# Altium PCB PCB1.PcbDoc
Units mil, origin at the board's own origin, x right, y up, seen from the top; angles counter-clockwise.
Board outline 2600 x 2600 mil, 4 copper layers (Top Layer, Layer 1, Layer 2, Bottom Layer), stack 68.756 mil thick; 75 components, 74 nets, 370 pads, 169 vias.
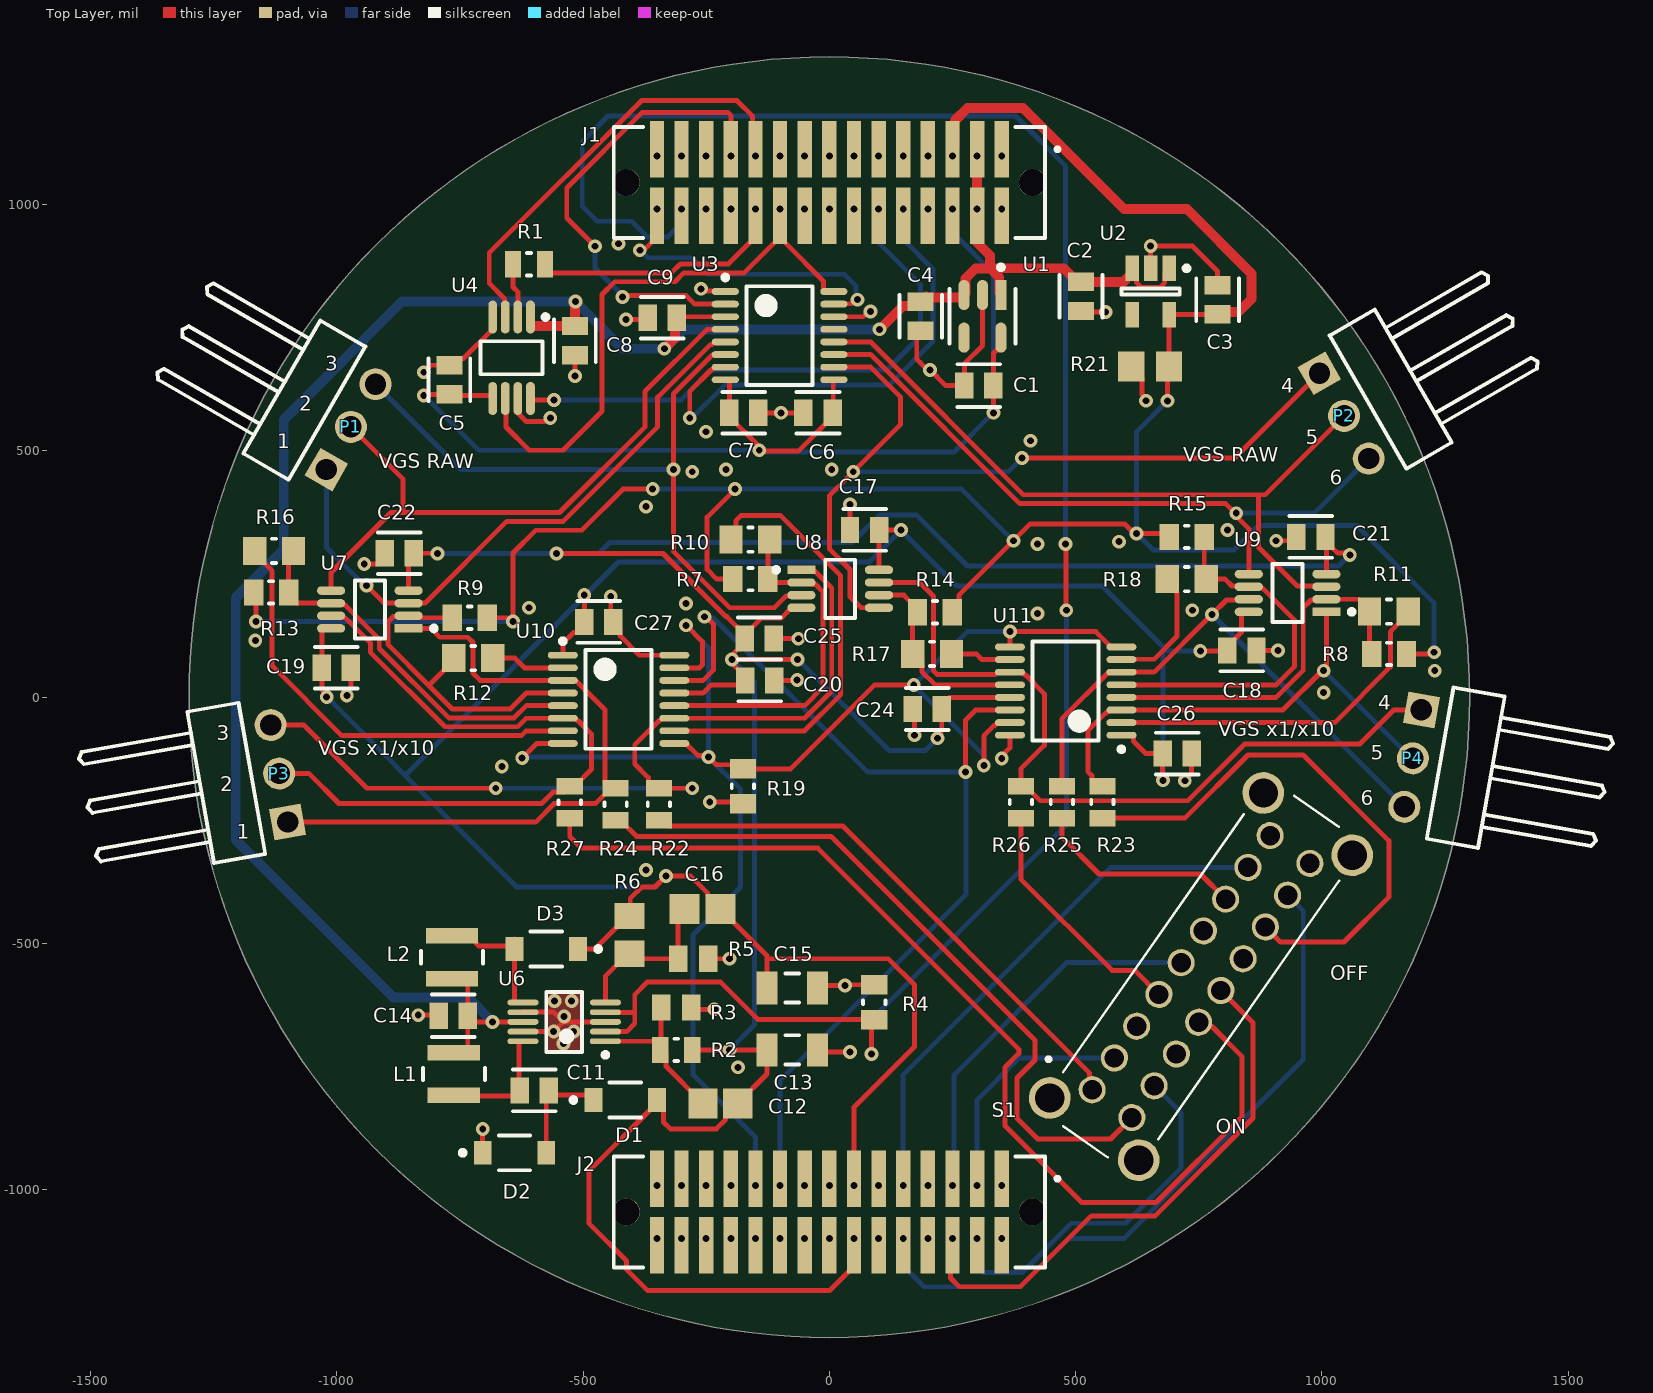
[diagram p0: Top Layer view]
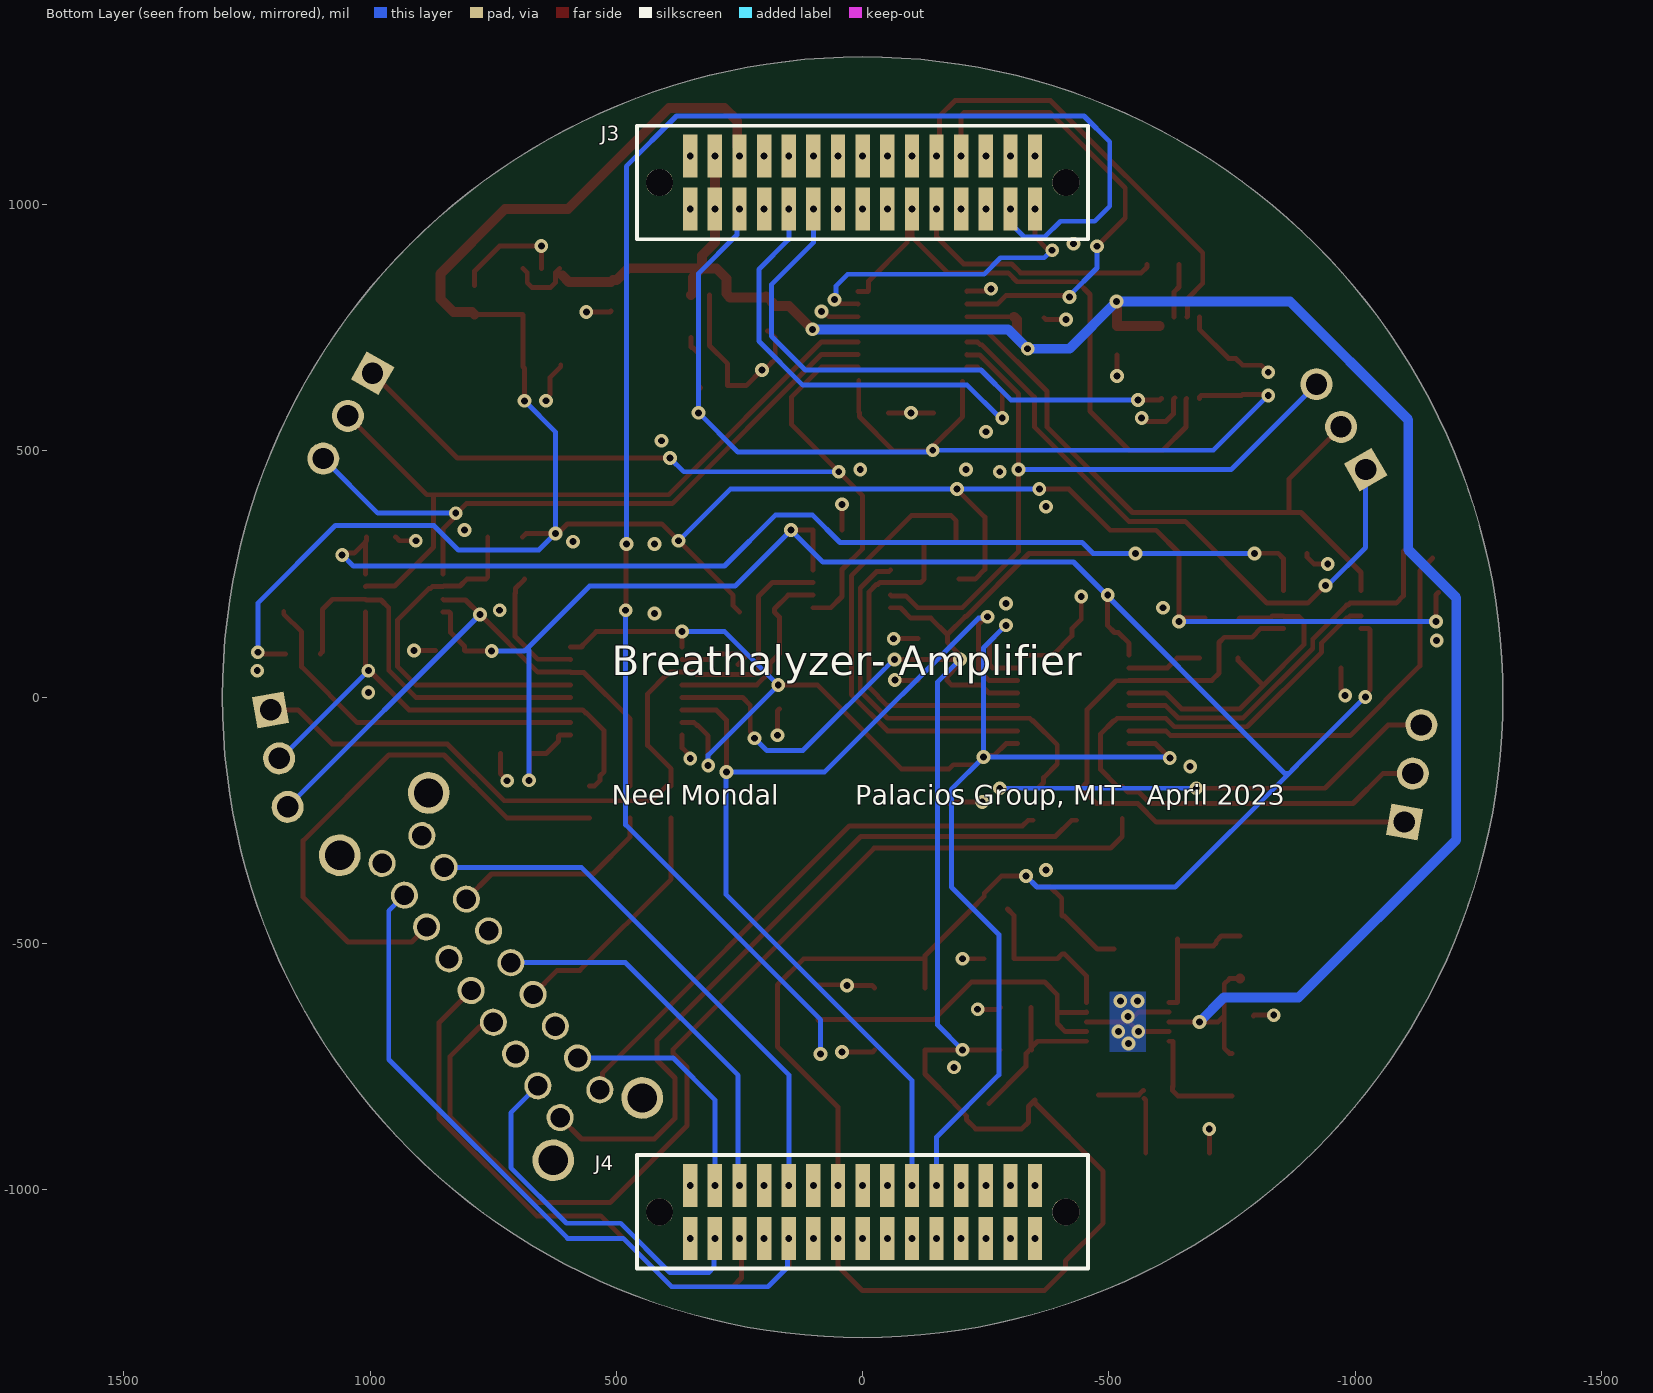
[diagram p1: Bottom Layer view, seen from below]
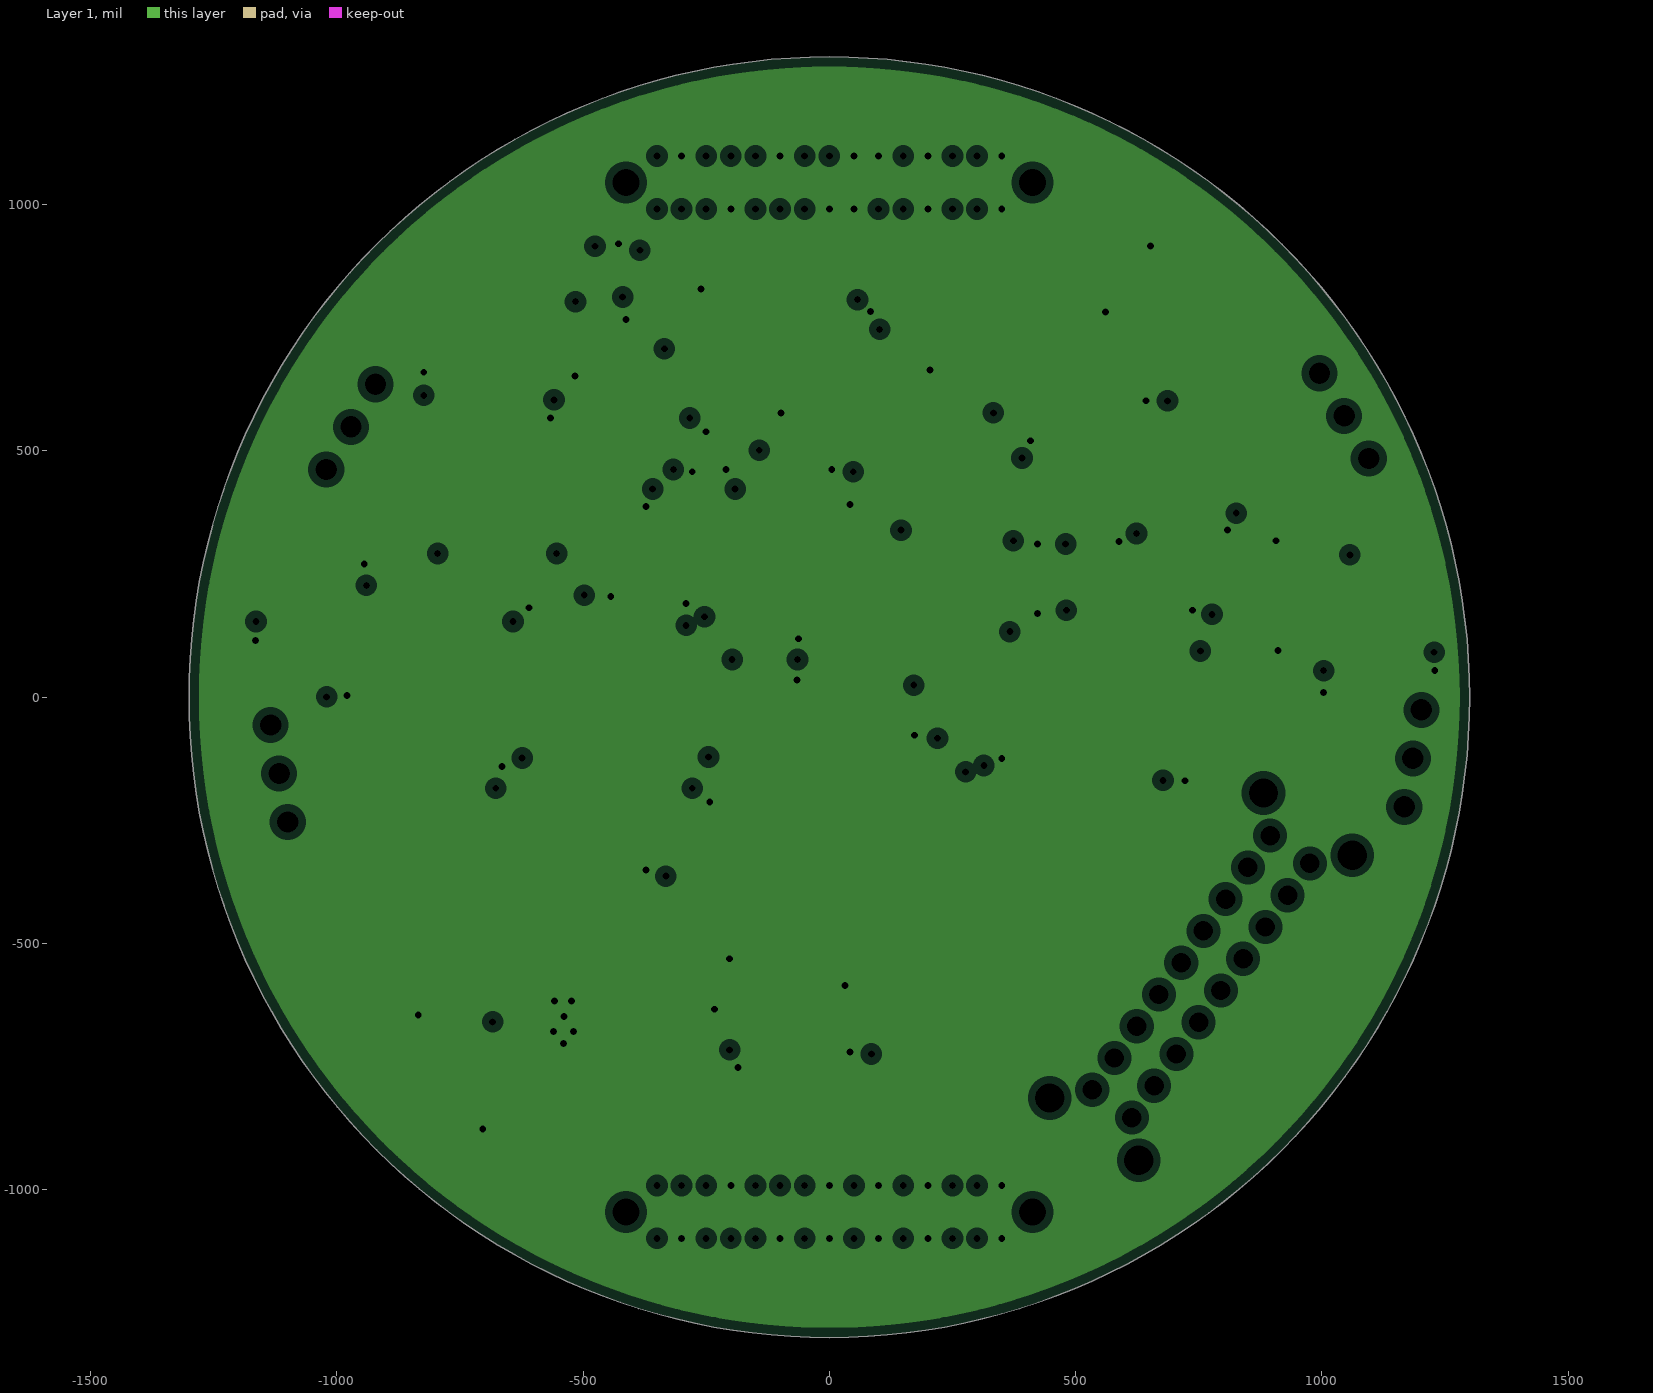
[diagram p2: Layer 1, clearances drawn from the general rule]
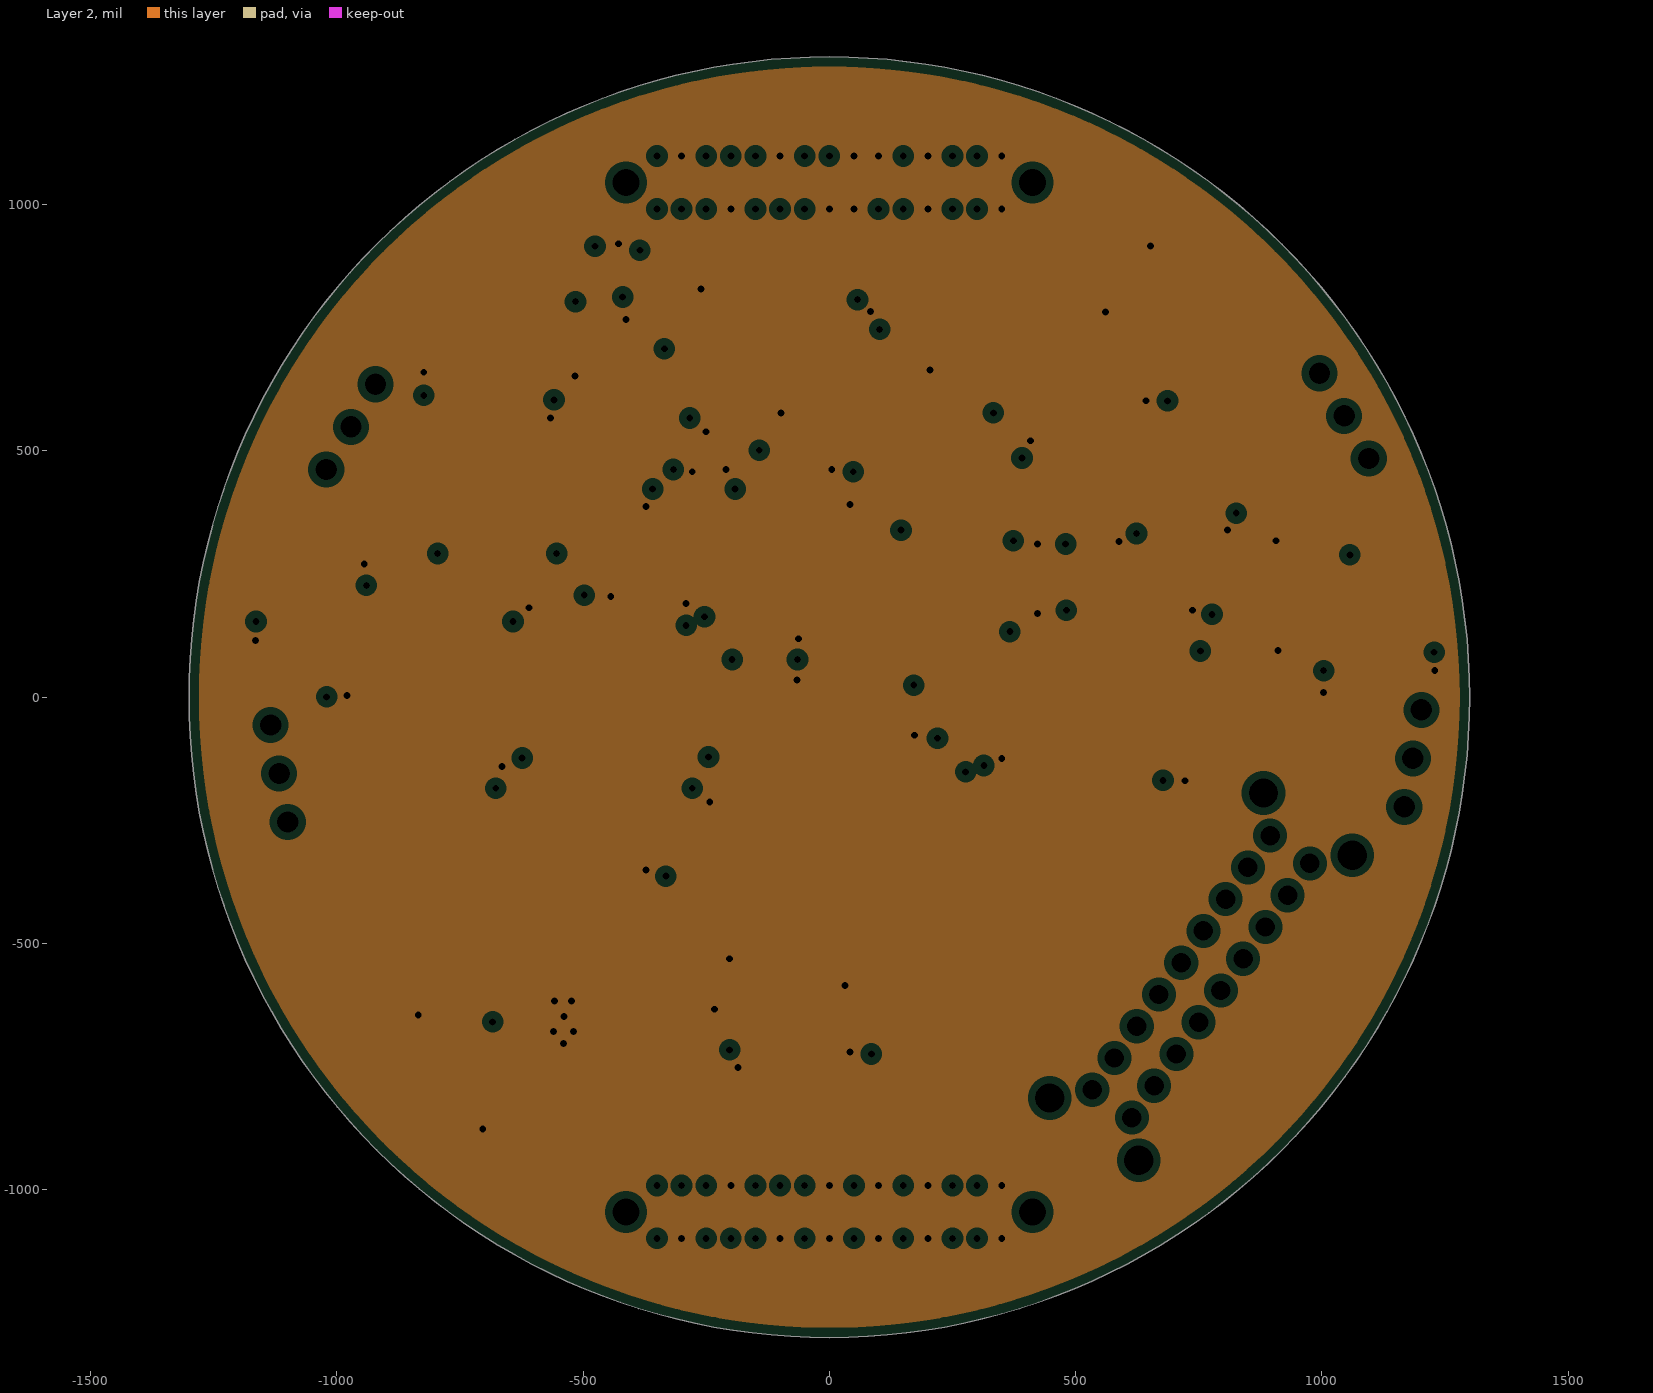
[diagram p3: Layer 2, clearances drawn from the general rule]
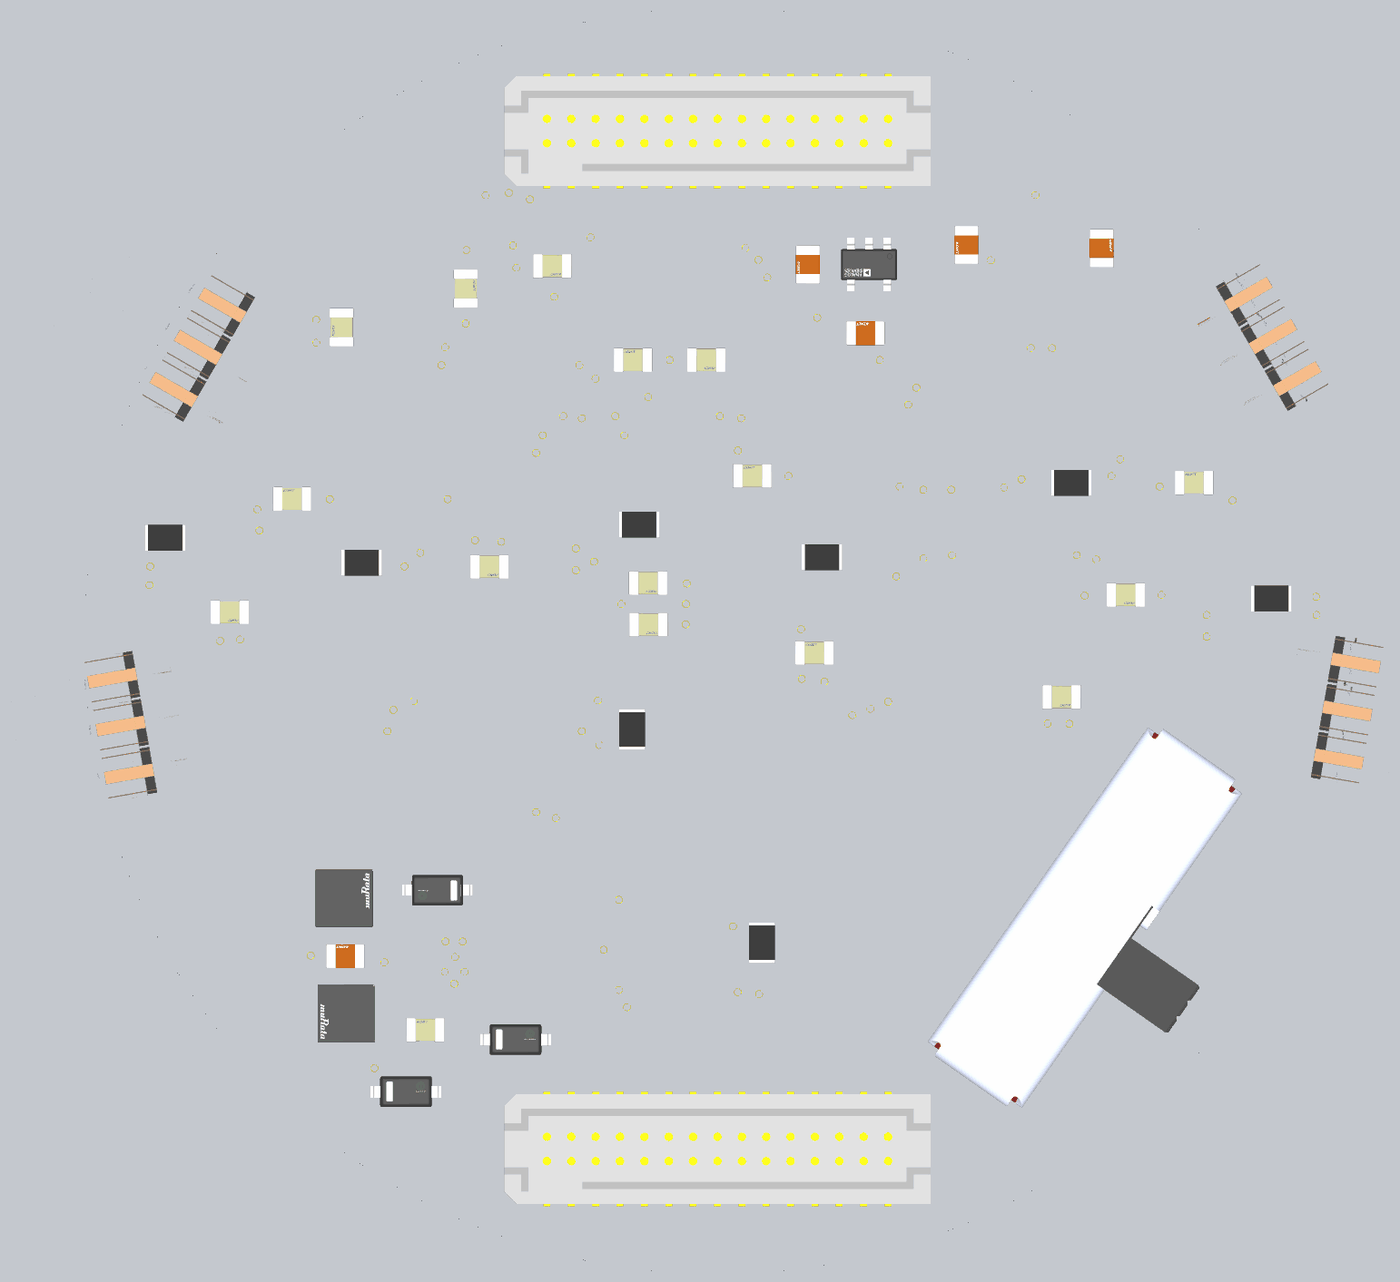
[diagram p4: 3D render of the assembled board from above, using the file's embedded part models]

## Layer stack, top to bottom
Top Solder: solder mask 0.5, Solder Resist, Dk 3.3
Top Layer: signal copper 0.7
Dielectric 1: prepreg 2.8, PP-006, Dk 4.1
Layer 1: plane copper 1.378, net GND
Dielectric1: core 59, FR-4, Dk 4.3
Layer 2: plane copper 1.378, net GND
Dielectric 2: prepreg 2.8, PP-006, Dk 4.1
Bottom Layer: signal copper 0.7
Bottom Solder: solder mask 0.5, Solder Resist, Dk 3.3

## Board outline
-1300,0 ccw(c0,0) 0,-1300 ccw(c0,0) 1300,0 ccw(c0,0) 0,1300 ccw(c0,0)

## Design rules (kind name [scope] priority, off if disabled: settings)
Clearance [All] p1: gap=8 ignorepadtopadclearanceinfootprint=FALSE except(6: SMDPad-SMDPad; 12: Arc-Via Track-Via)
DiffPairsRouting [All] p1: maxlimit=10 minlimit=10 mostfreqgap=10 toplayer_minwidth=10 toplayer_maxwidth=10 toplayer_prefwidth=10 bottomlayer_minwidth=10 bottomlayer_maxwidth=10 bottomlayer_prefwidth=10 maxuncoupledlength=500
HoleSize [All] p1: absolutevalues=TRUE maxlimit=300 minlimit=10 maxpercent=80.000 minpercent=20.000
MinimumAnnularRing [All] p1: minimumring=7
MinimumSolderMaskSliver [All] p1: minsoldermaskwidth=0
PasteMaskExpansion [All] p1: expansion=10
PlaneClearance [All] p1: clearance=15
PlaneConnect [All] p1: pad.planeconnectstyle=Relief pad.reliefexpansion=20 pad.reliefentries=4 pad.reliefconductorwidth=10 pad.reliefairgap=10 via.planeconnectstyle=Direct via.reliefexpansion=20 via.reliefentries=4 via.reliefconductorwidth=10 via.reliefairgap=10
PolygonConnect [All] p1: thpad.connectstyle=Relief thpad.reliefconductorwidth=10 thpad.reliefentries=4 thpad.polygonreliefangle="90 Angle" thpad.airgapwidth=10 smdpad.connectstyle=Relief smdpad.reliefconductorwidth=10 smdpad.reliefentries=4 smdpad.polygonreliefangle="90 Angle" smdpad.airgapwidth=10 via.connectstyle=Direct via.reliefconductorwidth=10 via.reliefentries=4 via.polygonreliefangle="90 Angle" via.airgapwidth=10
RoutingVias [All] p1: holewidth=14 width=28 viastyle="Through Hole" minholewidth=14 minwidth=28 maxholewidth=14 maxwidth=28
SMDNeckDown [All] p1: percent=150.000
SilkToSolderMaskClearance SilkscreenOverComponentPads [IsPad] p1: minsilkscreentomaskgap=0 clearancetoexposedcopper=TRUE
SolderMaskExpansion [All] p1: expansion=10 istentingtop=FALSE
Width [All] p1: maxlimit=30 minlimit=10 preferedwidth=10
23 further rules are at their usual default settings.

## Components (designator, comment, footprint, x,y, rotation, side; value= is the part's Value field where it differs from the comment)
C1 "4.7 uF" FP-C0805C475K3PACTU-MFG 303.55,632.61 r180 top
C2 "4.7 uF" FP-C0805C475K3PACTU-MFG 510.93,813.62 r270 top
C3 "4.7 uF" FP-C0805C475K3PACTU-MFG 788.14,806.63 r90 top
C4 "4.7 uF" FP-C0805C475K3PACTU-MFG 185.43,773.3 r270 top
C5 "100 nF" FP-C0805C-DN-MFG -771.4,644.43 r90 top value="0.10 μF"
C6 "100 nF" FP-C0805C-DN-MFG -22.98,577.3 r180 top value="0.10 μF"
C7 "100 nF" FP-C0805C-DN-MFG -173.44,577.3 r0 top value="0.10 μF"
C8 "100 nF" FP-C0805C-DN-MFG -516.6,724.07 r270 top value="0.10 μF"
C9 "100 nF" FP-C0805C-DN-MFG -338.91,770.32 r180 top value="0.10 μF"
C11 "100 nF" FP-C0805C-DN-MFG -599.3,-798.23 r0 top value="0.10 μF"
C12 "100 pF" CAPC2013X140X50ML20T25 -221.28,-825.33 r180 top
C13 "1 uF" CAPC3216X110X50LL20T25 -75.35,-716 r180 top
C14 "4.7 uF" FP-C0805C475K3PACTU-MFG -763.65,-646.88 r180 top
C15 "1 uF" CAPC3216X110X50LL20T25 -75.35,-590.33 r0 top
C16 "4.7 pF" CAPC2013X71X50ML20T25 -257.7,-430 r180 top
C17 "100 nF" FP-C0805C-DN-MFG 71.54,339.52 r0 top value="0.10 μF"
C18 "100 nF" FP-C0805C-DN-MFG 837.7,95.04 r180 top value="0.10 μF"
C19 "100 nF" FP-C0805C-DN-MFG -1000.79,59.61 r180 top value="0.10 μF"
C20 "100 nF" FP-C0805C-DN-MFG -142.28,119.39 r180 top value="0.10 μF"
C21 "100 nF" FP-C0805C-DN-MFG 977.8,325.4 r0 top value="0.10 μF"
C22 "100 nF" FP-C0805C-DN-MFG -872.87,292.18 r0 top value="0.10 μF"
C24 "100 nF" FP-C0805C-DN-MFG 198.75,-24.05 r0 top value="0.10 μF"
C25 "100 nF" FP-C0805C-DN-MFG -141.55,34.02 r180 top value="0.10 μF"
C26 "100 nF" FP-C0805C-DN-MFG 706.14,-114.6 r180 top value="0.10 μF"
C27 "100 nF" FP-C0805C-DN-MFG -467.94,152.85 r180 top value="0.10 μF"
D1 "MBR0530" FP-425-04-MFG -414.26,-817.92 r0 top
D2 "MBR0530" FP-425-04-MFG -639.2,-925.01 r0 top
D3 "MBR0530" FP-425-04-MFG -574.7,-511.32 r180 top
J1 "TFM-115-02-L-D" SAMTEC_TFM-115-02-L-D 0,1045 r180 top locked
J2 "TFM-115-02-L-D" SAMTEC_TFM-115-02-L-D 0,-1045 r180 top locked
J3 "SAMTEC-SFM-115-02-X-D-A" SAMTEC-SFM-115-02-X-D-A 0,1045 r180 bottom locked
J4 "SAMTEC-SFM-115-02-X-D-A" SAMTEC-SFM-115-02-X-D-A 0,-1045 r180 bottom locked
L1 "LQH3NPN100MMEL" FP-LQH3NPH_ME-MFG -762.28,-765.03 r270 top
L2 "LQH3NPN100MMEL" FP-LQH3NPH_ME-MFG -765.93,-528 r90 top
P1 "DNP" 61300311021 -1065.71,603.29 r240 top locked
P2 "DNP" 61300311021 1139.57,625.61 r120 top locked
P3 "DNP" 61300311021 -1224.37,-174.02 r280 top locked
P4 "DNP" 61300311021 1292.09,-143.15 r80 top locked
R1 "100" RESC2013X50X30LL20T20 -609.72,878.95 r0 top
R2 "196k" RESC2013X50X30LL20T20 -310.85,-716 r0 top
R3 "24.9k" RESC2013X70X40LL20T20 -310.85,-629.7 r180 top
R4 "10k" RESC2013X60X35NL10T20 91.23,-619.2 r270 top
R5 "24.9k" RESC2013X70X40LL20T20 -276.4,-531 r0 top
R6 "220k" RESC2013X70X40ML20T20 -405.41,-482.62 r270 top
R7 "10k" RESC2013X60X35NL10T20 -160.25,239.7 r180 top
R8 "10k" RESC2013X60X35NL10T20 1136.45,87.89 r0 top
R9 "10k" RESC2013X60X35NL10T20 -730.06,161.26 r0 top
R10 "91k" RESC2013X60X35ML10T20 -160.25,319.84 r180 top
R11 "91k" RESC2013X60X35ML10T20 1136.05,173.63 r0 top
R12 "91k" RESC2013X60X35ML10T20 -722.91,79.29 r0 top
R13 "10k" RESC2013X60X35NL10T20 -1133.28,212.62 r180 top
R14 "10k" RESC2013X60X35NL10T20 214.49,172.54 r0 top
R15 "10k" RESC2013X60X35NL10T20 725.83,325.4 r180 top
R16 "91k" RESC2013X60X35ML10T20 -1127.38,297.09 r180 top
R17 "91k" RESC2013X60X35ML10T20 208.59,87.89 r0 top
R18 "91k" RESC2013X60X35ML10T20 725.68,239.7 r180 top
R19 "10k" RESC2013X60X35NL10T20 -175.45,-180.91 r270 top
R21 "470" RESC2013X70X40ML20T20 651.43,671 r0 top
R22 "100" RESC2013X50X30LL20T20 -345.91,-217.33 r270 top
R23 "100" RESC2013X50X30LL20T20 554.46,-212.97 r270 top
R24 "100" RESC2013X50X30LL20T20 -433.95,-217.33 r270 top
R25 "100" RESC2013X50X30LL20T20 472.14,-212.97 r270 top
R26 "100" RESC2013X50X30LL20T20 389,-212.97 r270 top
R27 "100" RESC2013X50X30LL20T20 -527,-213.39 r270 top
S1 "EG6201" SW_EG6201 754.65,-567.27 r55 top
U1 "ADP150AUJZ-2.0-R7" FP-UJ-5-IPC_B 310.96,773.3 r270 top
U2 "LD39015M10R" SOT23-5L_M 652.41,823.47 r270 top
U3 "AD5328BRUZ" RU-16_L -100.98,733.99 r0 top
U4 "AD7274BRMZ" RM-8_N -645.16,689.05 r270 top
U6 "LT1945EMS#PBF" LT-MS-10_N -538.28,-659.23 r180 top
U7 "ADA4522-2ARMZ" FP-RM-8-IPC_C -932.84,178 r180 top
U8 "ADA4522-2ARMZ" FP-RM-8-IPC_C 22.07,220.01 r0 top
U9 "ADA4522-2ARMZ" FP-RM-8-IPC_C 930.41,211.56 r180 top
U10 "ADG5433BRUZ" ADI-RU-16_N -427.93,-4.37 r0 top
U11 "ADG5433BRUZ" ADI-RU-16_N 479.76,12.36 r180 top

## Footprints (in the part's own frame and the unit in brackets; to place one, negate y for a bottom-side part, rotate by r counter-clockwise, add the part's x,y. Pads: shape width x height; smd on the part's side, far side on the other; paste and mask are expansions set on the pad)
61300311021 [mm] "Pin Header, pitch 2.54 mm, THT, Angled, single row, 3p"
  rect 1.65x1.65 hole 1.1: 1(2.54,2.77)
  round 1.65 hole 1.1: 2(0,2.77) 3(-2.54,2.77)
  silkscreen extent -3.96,-7.27 3.96,1.34, body extent -3.81,-7.27 3.81,3.09, height 2.58
ADI-RU-16_N [mm] "SOP, 16-Leads, Body 5x4.4mm, Pitch 0.65mm, IPC Medium Density"
  oval 1.55x0.35 smd: 1(-2.875,2.275) 2(-2.875,1.625) 3(-2.875,0.975) 4(-2.875,0.325) 5(-2.875,-0.325) 6(-2.875,-0.975) 7(-2.875,-1.625) 8(-2.875,-2.275) 9(2.875,-2.275) 10(2.875,-1.625) 11(2.875,-0.975) 12(2.875,-0.325) 13(2.875,0.325) 14(2.875,0.975) 15(2.875,1.625) 16(2.875,2.275)
  silkscreen extent -3,-2.55 1.7,3.12, body extent -2.25,-2.55 2.25,2.55, height 1.2
CAPC2013X71X50ML20T25 [mm] "Chip Capacitor, 2-Leads, Body 2.01x1.25mm, IPC Low Density"
  rect 1.55x1.55 smd: 1(-0.925,0) 2(0.925,0)
  body extent -1.1,-0.73 1.11,0.73, height 0.71
CAPC2013X140X50ML20T25 [mm] "Chip Capacitor, 2-Leads, Body 2.00x1.25mm, IPC Low Density"
  rect 1.5x1.55 smd: 1(-0.9,0) 2(0.9,0)
  body extent -1.1,-0.72 1.1,0.72, height 1.4
CAPC3216X110X50LL20T25 [mm] "Chip Capacitor, 2-Leads, Body 3.20x1.60mm, IPC High Density"
  rect 1.1x1.7 smd: 1(-1.3,0) 2(1.3,0)
  silkscreen extent -0.35,-0.75 0.35,0.75, body extent -1.7,-0.9 1.7,0.9, height 1.1
FP-425-04-MFG [mil]
  rect 36x48 smd paste+0 mask+0: 1(-64.5,0) 2(64.5,0)
  silkscreen extent -110,-35 32,35, body extent -86,-39 86,39, height 10
FP-C0805C475K3PACTU-MFG [mm]
  rect 0.95x1.35 smd paste+0 mask+0: 1(-0.75,0) 2(0.75,0)
  silkscreen extent -1.1,-1.1 1.1,1.1, body extent -1.4,-0.85 1.4,0.85, height 0.25
FP-C0805C-DN-MFG [mm]
  rect 0.95x1.35 smd paste+0 mask+0: 1(-0.75,0) 2(0.75,0)
  silkscreen extent -1.1,-1.07 1.1,1.07, body extent -1.4,-0.85 1.4,0.85, height 0.25
FP-LQH3NPH_ME-MFG [mm]
  rect 0.8x2.7 smd paste+0 mask+0: 1(-1.1,0) 2(1.1,0)
  silkscreen extent -0.33,-1.6 0.33,1.6, body extent -1.7,-1.7 1.7,1.7, height 0.25
FP-RM-8-IPC_C [mm]
  rect 1.454x0.436 smd paste+0 mask+0: 1(-2,0.975)
  rrect100% 1.454x0.436 smd paste+0 mask+0: 2(-2,0.325) 3(-2,-0.325) 4(-2,-0.975) 5(2,-0.975) 6(2,-0.325) 7(2,0.325) 8(2,0.975)
  silkscreen extent -3.43,-1.5 0.77,1.5
FP-UJ-5-IPC_B [mm]
  rect 1.554x0.572 smd paste+0 mask+0: 1(-1.1,0.95)
  rrect100% 1.554x0.572 smd paste+0 mask+0: 2(-1.1,0) 3(-1.1,-0.95) 4(1.1,-0.95) 5(1.1,0.95)
  silkscreen extent -2.65,-1.7 1.4,1.7, body extent -2.13,-1.7 2.13,1.7, height 0.25
LT-MS-10_N [mm] "SOP, 10-Leads, Body 3.1x3.1mm, Pitch 0.5mm, IPC Medium Density"
  oval 1.6x0.3 smd: 1(-2.125,1) 2(-2.125,0.5) 3(-2.125,0) 4(-2.125,-0.5) 5(-2.125,-1) 6(2.125,-1) 7(2.125,-0.5) 8(2.125,0) 9(2.125,0.5) 10(2.125,1)
  silkscreen extent -2.25,-1.55 0.92,1.82, body extent -1.55,-1.55 1.55,1.55, height 1.1
RESC2013X50X30LL20T20 [mm] "Chip Resistor, 2-Leads, Body 2.00x1.25mm, IPC High Density"
  rect 0.85x1.35 smd: 1(-0.825,0) 2(0.825,0)
  silkscreen extent -0.1,-0.58 0.1,0.58, body extent -1.1,-0.73 1.1,0.73, height 0.5
RESC2013X60X35ML10T20 [mm] "Chip Resistor, 2-Leads, Body 2.00x1.25mm, IPC Low Density"
  rect 1.2x1.45 smd: 1(-1,0) 2(1,0)
  silkscreen extent -0.1,-0.63 0.1,0.63, body extent -1.05,-0.67 1.05,0.67, height 0.6
RESC2013X60X35NL10T20 [mm] "Chip Resistor, 2-Leads, Body 2.1x1.35mm, IPC Medium Density"
  rect 1x1.35 smd: 1(-0.9,0) 2(0.9,0)
  silkscreen extent -0.1,-0.58 0.1,0.58, body extent -1.05,-0.68 1.05,0.67, height 0.6
RESC2013X70X40LL20T20 [mm] "Chip Resistor, 2-Leads, Body 2.00x1.25mm, IPC High Density"
  rect 0.95x1.35 smd: 1(-0.775,0) 2(0.775,0)
  body extent -1.1,-0.73 1.1,0.72, height 0.7
RESC2013X70X40ML20T20 [mm] "Chip Resistor, 2-Leads, Body 2.00x1.25mm, IPC Low Density"
  rect 1.35x1.55 smd: 1(-0.975,0) 2(0.975,0)
  body extent -1.1,-0.73 1.1,0.73, height 0.7
RM-8_N [mm] "TSOP, 8-Leads, Body 3x3mm, Pitch 0.65mm, IPC Medium Density"
  oval 1.7x0.45 smd: 1(-2.1,0.975) 2(-2.1,0.325) 3(-2.1,-0.325) 4(-2.1,-0.975) 5(2.1,-0.975) 6(2.1,-0.325) 7(2.1,0.325) 8(2.1,0.975)
  silkscreen extent -2.22,-1.6 0.85,1.88, body extent -1.6,-1.6 1.6,1.6, height 1.1
RU-16_L [mm] "TSOP, 16-Leads, Body 5x4.4mm, Pitch 0.65mm, IPC High Density"
  oval 1.4x0.35 smd: 1(-2.8,2.275) 2(-2.8,1.625) 3(-2.8,0.975) 4(-2.8,0.325) 5(-2.8,-0.325) 6(-2.8,-0.975) 7(-2.8,-1.625) 8(-2.8,-2.275) 9(2.8,-2.275) 10(2.8,-1.625) 11(2.8,-0.975) 12(2.8,-0.325) 13(2.8,0.325) 14(2.8,0.975) 15(2.8,1.625) 16(2.8,2.275)
  silkscreen extent -2.92,-2.55 1.7,3.12, body extent -2.25,-2.55 2.25,2.55, height 1.2
SAMTEC-SFM-115-02-X-D-A [mm]
  rect 0.74x2.22 smd mask+0: 1(-8.89,1.365) 2(-8.89,-1.365) 3(-7.62,1.365) 4(-7.62,-1.365) 5(-6.35,1.365) 6(-6.35,-1.365) 7(-5.08,1.365) 8(-5.08,-1.365) 9(-3.81,1.365) 10(-3.81,-1.365) 11(-2.54,1.365) 12(-2.54,-1.365) 13(-1.27,1.365) 14(-1.27,-1.365) 15(0,1.365) 16(0,-1.365) 17(1.27,1.365) 18(1.27,-1.365) 19(2.54,1.365) 20(2.54,-1.365) 21(3.81,1.365) 22(3.81,-1.365) 23(5.08,1.365) 24(5.08,-1.365) 25(6.35,1.365) 26(6.35,-1.365) 27(7.62,1.365) 28(7.62,-1.365) 29(8.89,1.365) 30(8.89,-1.365)
  round 1.4 hole 1.4 unplated: ""(-10.478,0) ""(10.478,0)
  silkscreen extent -11.63,-2.93 11.63,2.93, body extent -11.11,-2.16 11.11,2.04, height 4.7
SAMTEC_TFM-115-02-L-D [mm]
  rect 0.74x2.92 smd: 01(-8.89,-1.715) 02(-8.89,1.715) 03(-7.62,-1.715) 04(-7.62,1.715) 05(-6.35,-1.715) 06(-6.35,1.715) 07(-5.08,-1.715) 08(-5.08,1.715) 09(-3.81,-1.715) 10(-3.81,1.715) 11(-2.54,-1.715) 12(-2.54,1.715) 13(-1.27,-1.715) 14(-1.27,1.715) 15(0,-1.715) 16(0,1.715) 17(1.27,-1.715) 18(1.27,1.715) 19(2.54,-1.715) 20(2.54,1.715) 21(3.81,-1.715) 22(3.81,1.715) 23(5.08,-1.715) 24(5.08,1.715) 25(6.35,-1.715) 26(6.35,1.715) 27(7.62,-1.715) 28(7.62,1.715) 29(8.89,-1.715) 30(8.89,1.715)
  silkscreen extent -11.87,-2.86 11.11,2.86, body extent -11.11,-3.05 11.11,2.92, height 5.71
SOT23-5L_M [mm] "SOT23, 5-Leads, Body 2.9x1.6mm, Pitch 0.95mm, Lead Span 2.8mm, IPC Low Density"
  rect 1.3x0.7 smd: 1(-1.2,0.95) 2(-1.2,0) 3(-1.2,-0.95) 4(1.2,-0.95) 5(1.2,0.95)
  silkscreen extent -1.32,-1.5 0.15,1.98, body extent -0.87,-1.5 0.87,1.5, height 1.45
SW_EG6201 [mm]
  round 1.4 hole 1: 1(-8,1.25) 2(-6,1.25) 3(-4,1.25) 4(-2,1.25) 5(0,1.25) 6(2,1.25) 7(4,1.25) 8(6,1.25) 9(8,1.25) 10(-8,-1.25) 11(-6,-1.25) 12(-4,-1.25) 13(-2,-1.25) 14(0,-1.25) 15(2,-1.25) 16(4,-1.25) 17(6,-1.25) 18(8,-1.25)
  round 2.15 hole 1.5: S1(-9.6,2.8) S2(-9.6,-2.8) S3(9.6,2.8) S4(9.6,-2.8)
  silkscreen extent -10.4,-3 10.4,4.1, body extent -10.41,-6.98 10.39,3.02, height 5

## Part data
C1 C2 C3 C4 C14: library part CMP-2007-01010-2, "CAP CER 4.7UF 25V X5R 0805", Capacitance=4.7uF, Case Code (Imperial)=0805, Case Code (Metric)=2012, Dielectric=X5R, Dielectric Material=Ceramic, Max Operating Temperature=85°C, Min Operating Temperature=-55°C, Package Quantity=2500, Tolerance=10%, Voltage=25V
C5 C6 C7 C8 C9 C11 C17 C18 C19 C20 C21 C22 C24 C25 C26 C27: library part CMP-2007-00279-2, "CAP CER 0.1UF 50V X7R 0805", Capacitance="0.10 μF", Manufacturer=KEMET, Manufacturer Part Number=C0805C104K5RACTU, Package=C0805C-DN, Temperature="-55°C to +125°C", Temperature Characteristic=X7R, Temperature Coefficient=30ppm/°C, Temperature Range High=+125°C, Temperature Range Low=-55°C, Tolerance=0.1, Voltage Rating="50 V"
C12: library part CMP-2007-04713-1, "08055C101KAT2A", Manufacturer="AVX Interconnect / Elco"
C13 C15: library part CMP-2000-06011-1, "C1206C105K5RACTU", Capacitance=1uF, Capacitance - nF=1000nF, Case Code - in=1206, Case Code - mm=3216, Case Height=1mm, Case Length=3.2mm, Case Width=1.6mm, Dielectric=X7R, Manufacturer=Kemet, Maximum Operating Temperature=+125C, Minimum Operating Temperature=-55C, Operating Temperature Range=-55Cto+125C, Package / Case=1206(3216metric), Package Description="2-Pin Surface Mount Device, Body 3.2 x 1.6 mm", Temperature Coefficient / Code=+/-15%, Tolerance=10%, Voltage Rating=50V
C16: library part CMP-1036-00549-2, "08055A4R7CAT2A", Manufacturer="AVX Interconnect / Elco"
D1 D2 D3: library part CMP-2000-05113-2, "DIODE SCHOTTKY 30V 500MA SOD123", Average Rectified Current=500mA, Forward Voltage=430mV, Max Forward Surge Current (Ifsm)=5.5A, Max Operating Temperature=150°C, Max Repetitive Reverse Voltage (Vrrm)=30V, Max Reverse Leakage Current=130uA, Min Operating Temperature=-65°C, Package Quantity=1
J1 J2 J3 J4: Package=None
L1 L2: library part CMP-06042-002074-1, "Wire Wound Ferrite Inductor for Power Lines 10μH ±20% 0.228Ω 1280mA 1212", Case Code (Imperial)=1212, Case Code (Metric)=3030, Current Rating=1.28A, DC Resistance (DCR)=228mR, Inductance=10uH, Max Operating Temperature=85°C, Min Operating Temperature=-40°C, Resistor Type=Wirewound, Saturation Current=810mA, Self Resonant Frequency=20MHz, Test Frequency=1MHz, Tolerance=20%
P1 P2 P3 P4: library part CMP-1502-01061-1, "THT Angled Pin Header WR-PHD, Pitch 2.54 mm, Single Row, 3 pins", Contact Resistance=20mOhm, Manufacturer="Wurth Elektronik", Operating Temperature=-40to105degC, Package Reference=61300311021, Rated Current=3A, Withstanding Voltage=500VAC, Working Voltage=250VAC
R1 R22 R23 R24 R25 R26 R27: library part CMP-2001-04901-1, Manufacturer="Vishay Dale", Part Number=CRCW0805100RFKEA
R2: library part CMP-2001-04310-1, Manufacturer="Vishay Dale", Part Number=CRCW0805196KFKEA
R3 R5: library part CMP-2001-00073-1, Manufacturer=Panasonic, Part Number=ERJ-6ENF2492V
R4 R7 R8 R9 R13 R14 R15 R19: library part CMP-1659-00013-4, "Chip Resistor, 10 KOhm, +/- 1%, 0.125 W, -55 to 155 degC, 0805 (2012 Metric), RoHS, Tape and Reel", Manufacturer=Yageo, Max Operating Temperature="155 degC", Min Operating Temperature="-55 degC", Package Quantity=5000, Voltage Rating="150 V"
R6: library part CMP-2001-00522-1, Manufacturer=Panasonic, Part Number=ERJ6ENF2203V
R10 R11 R12 R16 R17 R18: library part CMP-2001-01407-1, Manufacturer=Yageo, Part Number=RC0805JR-0791KL
R21: library part CMP-2001-00549-5, "Chip Resistor, 470 Ohm, +/- 1%, 0.125 W, -55 to 155 degC, 0805 (2012 Metric), RoHS, Tape and Reel", Manufacturer=Panasonic, Max Operating Temperature="155 degC", Min Operating Temperature="-55 degC", Package Quantity=1, Voltage Rating="150 V"
S1: "Slide Switch 6PDT Through Hole, Right Angle", Package=None
U1: library part CMP-09138-000207-1, "IC REG LINEAR 2V 150MA 5TSOT", Case/Package=SOT-23-5, Dropout Voltage=105mV, Max Input Voltage=5.5V, Max Operating Temperature=125°C, Max Output Current=150mA, Max Supply Current=320uA, Min Current Limit=190mA, Min Input Voltage=2.2V, Min Operating Temperature=-40°C, Min Output Voltage=2V, Operating Supply Current=10uA, Power Supply Rejection Ratio (PSRR)=70dB, Quiescent Current=22uA
U2: library part CMP-0244-00345-1, "150 mA Low Quiescent Current Low Noise Voltage Regulator, 1.0V, 5-Pin SOT-23, Tape and Reel"
U3: library part CMP-0318-02011-2, "Octal 12-Bit Voltage Output Digital-to-Analog Converter, 2.5 to 5.5 V, -40 to +125 degC, RU-16, Pb-Free, Tube", Generic Part Number=AD5328, Manufacturer="Analog Devices"
U4: library part CMP-0313-01921-2, "Single 12-Bit Analog-to-Digital Converter with Serial, SPI Interface, 3MSPS, -40 to +125 degC, RM-8, Pb-Free, Tube", Generic Part Number=AD7274, Manufacturer="Analog Devices"
U6: library part CMP-0478-00153-1, "Dual Micropower DC/DC Converter with Positive and Negative Outputs, 1.2 to 15 V Vin, 10-pin SOP (MS-10), -40 to 85 degC, Pb-Free", Manufacturer="Linear Technology"
U7 U8 U9: library part CMP-09116-000003-2, "IC OPAMP ZERO-DRIFT 2 CIRC 8MSOP", Case/Package=MSOP, Input Bias Current=50pA, Input Offset Voltage (Vos)=1.5uV, Max Dual Supply Voltage=27.5V, Max Operating Temperature=125°C, Max Supply Voltage=55V, Min Dual Supply Voltage=2.25V, Min Operating Temperature=-40°C, Min Supply Voltage=4.5V, Operating Supply Current=830uA, Output Current per Channel=32mA, Power Supply Rejection Ratio (PSRR)=150dB, Voltage Gain=137dB
U10 U11: library part CMP-0794-00021-1, "High Voltage Latch-Up Proof, Triple SPDT Switches, 12.5 Ohm Ron, 16-pin SOP (RU-16), Tube", Manufacturer="Analog Devices"

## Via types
v1: diameter 28, hole 14, Top Layer to Bottom Layer, tented both sides, 169 vias

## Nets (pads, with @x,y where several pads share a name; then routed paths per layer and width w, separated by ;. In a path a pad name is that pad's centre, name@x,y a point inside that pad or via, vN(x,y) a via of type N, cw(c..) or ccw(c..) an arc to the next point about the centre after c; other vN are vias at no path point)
1V_REF: C3.1 J1.05 J3.5 R7.2 R8.2 R9.2 R13.2 R14.2 R15.2 R21.2 U2.5 | length 5053.1
  Top Layer w10: R13.2 -1163.98,207.88 v1(-1163.98,153.58) ; R9.2 -654.75,161.26 -647.07,153.58 v1(-642.2,153.58) -642.2,292.76 -596.02,338.94 -502.51,338.94 -418.95,422.51 v1(-358.59,422.51) ; R7.2 -228.46,239.7 -248.15,259.38 -248.15,365.67 v1(-191.31,422.51) ; R14.2 263.05,185.67 263.05,206.88 v1(373.7,317.53) 408.15,351.98 599.35,351.98 618.92,332.4 v1(623.79,332.4) 683.39,332.4 R15.2 ; v1(686.52,601.68) 686.52,667.7 R21.2 U2.5 690.69,777.1 C3.1 ; R8.2 1224.71,87.89 v1(1228.03,91.21)
  Top Layer w20: J1.05 254.57,1117.09 254.57,1170.21 280.36,1196 393.41,1196 598.15,991.26 725.83,991.26 857.38,859.7 857.38,808.7 830.81,782.13 793.18,782.13 C3.1
  Bottom Layer w10: v1(-1163.98,153.58) v1(-642.2,153.58) ; v1(-358.59,422.51) v1(-191.31,422.51) 268.72,422.51 v1(373.7,317.53) ; v1(686.52,601.68) 623.79,538.94 v1(623.79,332.4) 657.37,298.83 820.84,298.83 870.54,348.53 1070.53,348.53 1228.03,191.03 v1(1228.03,91.21)
  other v1: 250,1098.74
2V_REF: C1.1 C5.1 C6.1 C7.1 J1.06 J3.6 U1.5 U3.8 U3.9 U4.5 | length 2419.3
  Top Layer w10: v1(-823.41,612.72) -821.23,614.9 C5.1 ; C5.1@-769.14,612.65 -687.11,612.65 -683.54,609.08 U4.5 ; U3.8@-202.97,641.32 -202.97,569.43 -145.72,512.18 -145.72,504.77 -138.83,497.88 v1(-142.28,501.32) -140.4,499.44 -63.43,499.44 6.55,569.43 C6.1 7.9,578.66 U3.9@7.9,643.07 ; v1(333.08,577.3) 333.08,623.91 328.73,628.26 C1.1 333.08,697.66 345.57,710.16 347.2,710.16 348.36,711.33 U1.5
  Bottom Layer w10: v1(-823.41,612.72) -712.01,501.32 v1(-142.28,501.32) -138.83,497.88 253.65,497.88 v1(333.08,577.3) 333.08,860.69 255.35,938.42 255.35,985.91 v1(250,991.26)
3V3: C2.1 C4.1 C8.1 C9.1 C14.1 J1.03 J1.04 J3.3 J3.4 L1.1 L2.1 U1.1 U1.3 U2.1 U2.3 U3.3 U4.1 U6.8 | length 4569.1
  Top Layer w10: L2.1 -744.87,-571.31 -734.12,-582.06 C14.1 ; L1.1@-749.74,-723.39 -744.87,-723.39 -734.12,-712.64 C14.1 ; U6.8 v1(-683.54,-659.23) -721.78,-659.23 C14.1 ; C9.1@-307.32,772.38 U3.3 ; U2.3 623.79,861.93 623.79,841.58 633.25,832.12 671.58,832.12 681.04,841.58 681.04,861.93 U2.1
  Top Layer w20: U4.1@-603.21,753.6 C8.1 -516.6,801.99 v1(-515.48,803.11) ; v1(-334.97,707.33) -313.08,729.22 -313.08,766.62 C9.1 C9.1@-307.32,772.38 ; v1(102.15,746.79) 149.48,794.12 176.73,794.12 C4.1 ; C4.1@196.01,813.4 197.8,811.62 269.82,811.62 273.56,815.36 U1.3 ; U1.3@276.7,819.75 276.7,850.14 296.77,870.21 325.15,870.21 325.91,870.96 ; J1.03 J1.04 300,922.91 325.91,897 325.91,870.96 ; U1.1 344.94,820.04 344.94,851.93 325.91,870.96 ; U2.3@609.52,855.85 596.82,843.15 C2.1 507.23,846.85 499.36,846.85 475.24,870.96 325.91,870.96
  Bottom Layer w20: v1(-683.54,-659.23) -733.15,-609.63 -885.14,-609.63 -1204.98,-289.78 -1204.98,201.94 -1107.69,299.23 -1107.69,563.18 -867.76,803.11 v1(-515.48,803.11) -419.69,707.33 v1(-334.97,707.33) -295.51,746.79 v1(102.15,746.79)
  other v1: 300,991.26 300,1098.74
!ADC_CS: J1.21 J3.21 U4.3 | length 888.6
  Top Layer w10: U4.3 -659.43,773.21 -659.43,809.14 -690.37,840.09 -690.37,901.99 -381.37,1210.99 -187.46,1210.99 -155.61,1179.14 -155.61,1118.13 J1.21
  other v1: -150,1098.74
!BME_CS: J1.29 J3.29
  other v1: -350,1098.74
!CHIP_EN: J2.19 J4.19 U10.14 U11.14 | length 2065.5
  Top Layer w10: U10.14 -256.13,34.02 -235.43,54.71 -235.43,148.49 -250.29,163.35 v1(-253.28,163.35) ; v1(276.7,-151.68) 276.7,-46.3 296.98,-26.02 U11.14
  Bottom Layer w10: v1(-253.28,163.35) -250.47,160.55 -235.07,160.55 77.17,-151.68 v1(276.7,-151.68) ; v1(-100,-991.26) -100,-778.06 277.68,-400.37 v1@277.68,-152.01
!DAC_CS: J1.23 J3.23 U3.2 | length 953.2
  Top Layer w10: v1(-475.78,915.5) -533.11,972.83 -533.11,1033.8 -379.62,1187.29 -205.86,1187.29 -200,1181.43 J1.23 ; v1(-419.69,812.49) -416.82,815.36 -290.76,815.36 -273.37,797.97 U3.2
  Bottom Layer w10: v1(-475.78,915.5) -475.78,871.44 -419.69,815.36 v1(-419.69,812.49)
  other v1: -200,1098.74
!GATE_SHDN: J1.28 J3.28 R4.2 U6.2 U6.4 | length 4196.7
  Top Layer w10: U6.2 -411.62,-678.91 -395.09,-662.39 -395.09,-639.89 ; U6.4 -454.27,-639.89 -395.09,-639.89 ; v1(85.43,-724.5) 85.43,-660.42 R4.2 -144.51,-654.63 -221.28,-577.86 -369.1,-577.86 -395.09,-603.85 -395.09,-639.89 ; v1(479.76,310.98) 480.49,310.26 480.49,177.26 v1(481.21,176.53)
  Bottom Layer w10: v1(-300,991.26) -300,962.13 -327.57,934.56 -369.95,934.56 -401.65,966.26 -471.22,966.26 -501.64,996.67 -501.64,1127.45 -449.24,1179.84 377.89,1179.84 479.76,1077.97 v1(479.76,310.98) ; v1(85.43,-724.5) 85.43,-654.96 481.21,-259.18 v1(481.21,176.53)
+11V: C15.1 C16.1 C17.2 C18.2 C19.2 C26.2 C27.2 D3.1 J2.13 J4.13 R6.1 U7.8 U8.8 U9.8 U10.1 U11.1 | length 5172.2
  Top Layer w10: v1(-1020.48,0.55) -1020.48,5.42 -1030.32,15.27 C19.2 -1030.32,136.31 -1027.01,139.62 U7.8 ; U10.1 -541.12,109.2 -519.04,131.28 -511.17,131.28 -497.47,144.98 v1(-497.47,207.22) ; D3.1 -476.43,-511.32 -409.34,-444.23 R6.1 -404.15,-442.97 -404.15,-408.51 -380.94,-385.31 -353.85,-385.31 v1(-331.81,-363.27) -281.44,-363.27 -246.79,-397.91 -246.79,-404.49 C16.1 -126.53,-524.75 -126.53,-531 ; C15.1 -126.53,-531 ; J2.13 50,-832.37 173.15,-709.22 173.15,-584.41 119.74,-531 -126.53,-531 ; U8.8 100.82,339.28 C17.2 101.46,339.13 v1(145.47,339.13) v1@148.91,342.58 ; U11.1 615.55,-77.2 617.3,-78.95 617.3,-88.99 642.91,-114.6 C26.2 676.61,-168.08 v1(677.37,-168.83) ; v1(753.28,93.65) 806.78,93.65 C18.2 808.17,102.91 836.61,131.35 836.61,169.87 839.92,173.17 U9.8
  Bottom Layer w10: v1(-1020.48,0.55) -880.35,-139.57 -877.07,-142.86 -864.84,-155.09 ; v1(-331.81,-363.27) -353.85,-385.31 -634.62,-385.31 -864.84,-155.09 ; v1@145.47,338.94 258.68,225.73 554.45,225.73 681.29,98.88 ; v1(145.47,339.13) 80.73,274.39 -427.97,274.39 -857.45,-155.09 -864.84,-155.09 ; v1(677.37,-168.83) 677.37,94.96 681.29,98.88 ; v1(753.28,93.65) 686.52,93.65 681.29,98.88
  other v1: 50,-991.26
-11V: C12.1 C13.2 C20.2 C21.2 C22.2 C24.2 C25.2 D1.2 J2.14 J4.14 R2.2 U7.4 U8.4 U9.4 U10.13 U11.13 | length 6102.5
  Top Layer w10: U7.4 -854.09,281.43 C22.2 -795.79,292.18 v1(-795.3,291.68) ; v1(-553.67,291.68) -337.77,291.68 -209.71,163.63 -208.16,163.63 C20.2@-171.8,127.26 ; U10.13 -256.26,8.43 -239.53,25.16 -179.94,25.16 C25.2 -171.08,41.89 -193.95,64.76 -193.95,72.9 v1(-197.39,76.34) ; R2.2 v1(-202.45,-716) C13.2 -126.53,-765.03 -185.85,-824.35 C12.1 -210.37,-849.86 -210.37,-857.42 -229.47,-876.51 -322.9,-876.51 -336.76,-862.65 -336.76,-830.92 D1.2 -349.76,-823.92 -488.26,-962.42 -488.26,-1068 -411.62,-1144.64 -411.62,-1162.25 -368.86,-1205 0.43,-1205 50,-1155.43 J2.14 ; v1(-64.57,76.34) v1(-197.39,76.34) ; U8.4 -76.74,181.63 -97.75,160.61 -138.46,160.61 C20.2@-171.8,127.26 ; v1(219.53,-83.33) 219.53,-78.45 228.27,-69.71 C24.2 228.27,-16.18 244.02,-0.43 U11.13 ; C21.2 1007.33,317.53 C21.2@1009.17,315.69 ; U9.4 C21.2@1009.17,315.69 ; v1(1056.78,288.9) 1053.33,292.34 1032.51,292.34 C21.2@1009.17,315.69 ; v1(-197.39,76.34) -193.95,79.78 -193.95,89.37 -171.8,111.52 C20.2 C20.2@-171.8,127.26
  Bottom Layer w10: v1(-795.3,291.68) v1(-553.67,291.68) -467.99,291.68 -445.73,313.93 45.95,313.93 102.15,370.13 176.76,370.13 280.62,266.27 1034.15,266.27 v1(1056.78,288.9) ; v1(-202.45,-716) -152.12,-665.67 -152.12,31.06 v1(-197.39,76.34) ; v1(-64.57,76.34) -63.18,76.34 121.37,-108.2 194.65,-108.2 v1(219.53,-83.33)
  other v1: 50,-1098.74
DRAIN_SEL0: J2.22 J4.22
  other v1: -150,-1098.74
DRAIN_SEL1: J1.17 J3.17
  other v1: -50,1098.74
DRAIN_SEL2: J2.24 J4.24
  other v1: -200,-1098.74
DRAIN_SEL3: J1.15 J3.15
  other v1: 0,1098.74
DRAIN_SEL4: J1.18 J3.18
  other v1: -50,991.26
GATE1: J2.04 J4.4 S1.11 | length 753.3
  Bottom Layer w10: v1(300,-1098.74) 302,-1100.74 302,-1157.6 312.4,-1168 391.39,-1168 491.39,-1068 601.35,-1068 714.34,-955.01 714.34,-843.87 S1.11
GATE2: J2.06 J4.6 S1.14 | length 1117.6
  Top Layer w10: J2.06 246.14,-1116.38 246.14,-1179.14 264,-1197 387.85,-1197 531.82,-1053.03 661.63,-1053.03 860.23,-854.44 860.23,-660.76 S1.14
  other v1: 250,-1098.74
GATE3: J2.03 J4.3 S1.2 | length 487.9
  Bottom Layer w10: v1(300,-991.26) 300,-817.31 384.76,-732.55 S1.2
GATE4: J2.05 J4.5 S1.5 | length 781
  Bottom Layer w10: v1(250,-991.26) 252.8,-988.46 252.8,-767.68 481.43,-539.05 S1.5
GATE5: J2.10 J4.10 S1.17 | length 1466.5
  Top Layer w10: J2.10@150,-1155.43 J2.10
  Bottom Layer w10: v1(150,-1098.74) 152.56,-1101.3 152.56,-1157.44 192.12,-1197 387.85,-1197 486.11,-1098.74 599.05,-1098.74 962.13,-735.67 962.13,-433.67 S1.17
GATE6: J2.09 J4.9 S1.8 | length 1098.8
  Bottom Layer w10: v1(150,-991.26) 150,-766.72 571.17,-345.54 S1.8
GATE_AMP: J2.21 J4.21 R19.1 U10.8 U10.9 U10.15 U11.8 U11.9 U11.15 | length 3338.9
  Top Layer w10: v1(-623.61,-123.39) -594.15,-93.94 U10.8 ; U10.9 -291.12,-93.94 -266.9,-118.16 -248.75,-118.16 -229.81,-137.1 -183.82,-137.1 R19.1 -78.63,-145.48 91.37,24.52 v1(171.48,24.52) ; U10.15 -263.55,59.61 -257.7,65.47 -257.7,112.76 v1(-290.79,145.86) ; v1(313.68,-138.69) 313.68,-78.34 334.71,-57.31 336.23,-57.31 341.93,-51.61 U11.15 ; U11.9 v1(366.57,133.17) 541.17,133.17 568.61,105.73 568.61,103.68 570.35,101.93 U11.8
  Bottom Layer w10: v1(-623.61,-123.39) -621.82,-121.6 v1(-245.31,-121.6) ; v1(-290.79,145.86) -245.31,100.38 v1(-245.31,-121.6) ; v1(-150,-991.26) -150,-893.09 -276.39,-766.7 -276.39,-481.76 -179.94,-385.31 -179.94,-186.97 v1(-245.31,-121.6) ; v1(313.68,-138.69) 313.68,-117.68 v1(171.48,24.52) 280.13,133.17 v1(366.57,133.17)
GND: C1.2 C2.2 C3.2 C4.2 C5.2 C6.2 C7.2 C8.2 C9.2 C13.1 C14.2 C15.2 C17.1 C18.1 C19.1 C20.1 C21.1 C22.1 C24.1 C25.1 C26.1 C27.1 D2.1 J1.01 J1.02 J1.07 J1.08 J1.11 J1.13 J1.14 J1.16 J1.19 J1.24 J1.27 J2.01 J2.02 J2.07 J2.08 J2.11 J2.12 J2.15 J2.16 J2.20 J2.23 J2.28 J3.1 J3.2 J3.7 J3.8 J3.11 J3.13 J3.14 J3.16 J3.19 J3.24 J3.27 J4.1 J4.2 J4.7 J4.8 J4.11 J4.12 J4.15 J4.16 J4.20 J4.23 J4.28 R3.1 R4.1 R5.2 R19.2 R21.1 U1.2 U2.2 U3.1 U3.14 U4.4 U4.7 U6.3 U6.7 U6.9 U10.16 U11.16 | length 2808
  Top Layer w10: v1(-979.63,3.54) -979.63,8.41 -971.27,16.77 C19.1 ; v1(-944.15,270.51) -944.06,270.6 -916.1,270.6 -902.4,284.3 C22.1 ; v1(-834.58,-645.63) -794.43,-645.63 C14.2 ; v1(-823.41,659.79) -809.24,673.96 C5.2 -757.7,687.66 -743.01,687.66 -683.54,747.12 U4.4 ; D2.1 v1(-703.7,-876.51) ; U4.7@-633.84,607.85 U4.7 -630.88,604.9 -630.88,574.97 -615.82,559.91 -578.12,559.91 -571.29,566.74 v1(-566.42,566.74) ; U6.9 v1(-559.61,-678.91) v1@-539.92,-659.23 ; U6.7 -559.61,-639.54 v1@-539.92,-659.23 ; v1(-516.6,652.29) C8.2 ; U6.3 v1@-538.28,-659.23 ; v1(-443.68,204.3) -443.68,158.12 -424.71,139.15 -424.71,124.39 -385.52,85.2 U10.16 ; v1(-412.52,766.62) -372.14,766.62 C9.2 ; R3.1 -276.39,-633.65 v1(-233.43,-633.65) ; v1(-260.67,829.11) -255.8,829.11 -250.98,824.28 -211.94,824.28 U3.1 ; R5.2 v1(-202.45,-531) ; v1(-242.71,-212.97) -178.82,-212.97 R19.2 ; C7.2 v1(-98.21,577.3) C6.2 ; C20.1 -63.75,119.39 v1(-62.94,118.57) ; C25.1 -65.85,34.02 v1(-65.27,34.6) ; C13.1 -19.91,-720.25 v1(41.75,-720.25) ; C15.2 -19.25,-585.42 v1(31.72,-585.42) 33.37,-583.76 R4.1 ; U3.14 68.62,772.38 79.03,782.79 v1(83.9,782.79) ; C17.1 v1(42.02,391.51) ; C24.1 172.82,-27.66 v1(172.82,-77.2) ; C4.2@193.31,743.77 191.26,743.77 177.56,730.07 177.56,686.31 184.63,679.24 184.86,679.24 199.78,664.32 v1(204.65,664.32) 236.36,632.61 C1.2 274.02,676.79 310.96,713.73 U1.2 ; v1(350,-124.21) 350,-119.34 366.57,-102.77 U11.16 ; C2.2 512.9,782.13 v1(561.09,782.13) ; R21.1@613.04,674.93 R21.1 634.62,649.42 634.62,614.84 642.8,606.66 v1(642.8,601.79) ; U2.2 v1(652.41,915.99) 737,915.99 788.14,864.85 C3.2 ; v1(721.74,-169.66) 721.74,-169.41 735.67,-155.49 C26.1 ; C18.1 867.31,94.96 v1(910.73,94.96) ; v1(907.25,317.53) 940.4,317.53 C21.1 ; v1@-539.92,-659.23 v1@-538.28,-659.23 ; v1@-539.92,-659.23 v1@-538.28,-659.23
  other v1: -300,-1098.74 -100,-1098.74 0,-1098.74 100,-1098.74 200,-1098.74 350,-1098.74 -200,-991.26 0,-991.26 100,-991.26 200,-991.26 350,-991.26 -185.58,-751.43 -539.92,-703.21 -519.04,-678.91 -538.28,-648.41 -557.96,-616.68 -523.06,-616.68 -372.14,-351 -664.84,-141.01 1003.69,9.41 1229.13,53.8 -1165.31,115.01 422.46,169.87 737,176.53 -609.72,181.63 -290.76,190.48 422.46,310.98 587.92,315.69 808.36,339.13 -372.14,386.74 -278.37,457.64 -209.71,462.16 4.98,462.16 408.15,520.71 -250.29,538.94 -427.93,920.55 -200,991.26 0,991.26 50,991.26 200,991.26 350,991.26 -300,1098.74 -100,1098.74 50,1098.74 100,1098.74 200,1098.74 350,1098.74
GPIO13: J2.18 J4.18
  other v1: -50,-1098.74
HEAT_THERM_BUFF: J2.25 J4.25
  other v1: -250,-991.26
LOW_BATT: J2.29 J4.29
  other v1: -350,-991.26
MISO: J1.22 J3.22 R1.2 | length 511
  Top Layer w10: R1.2 -577.24,873.22 -565.51,861.49 -320.7,861.49 -302.7,879.49 -205.08,879.49 -150,934.57 J1.22
  other v1: -150,991.26
MOSI: J1.30 J3.30 U3.15 | length 638.8
  Top Layer w10: v1(-384.68,907.28) -381.24,910.73 -373.84,910.73 -350,934.57 J1.30 ; U3.15 9.98,798.69 44.07,798.69 52.47,807.09 v1(57.34,807.09)
  Bottom Layer w10: v1(-384.68,907.28) -383.66,907.28 -368.54,892.17 -279.89,892.17 -246.45,858.73 30.47,858.73 53.9,835.3 53.9,810.53 v1(57.34,807.09)
  other v1: -350,991.26
NetC11_1: C11.1 L1.2 U6.10 | length 233.2
  Top Layer w10: L1.2@-749.74,-810 -640.6,-810 C11.1 C11.1@-628.83,-790.36 ; C11.1@-630.22,-790.36 -630.22,-699.43 -629.38,-698.6 U6.10
NetC11_2: C11.2 D1.1 D2.2 | length 206.9
  Top Layer w10: D2.2 -574.7,-817.81 C11.2@-571.16,-814.28 ; C11.2 -560.73,-807.28 D1.1@-478.76,-807.28
NetC12_2: C12.2 R2.1 R3.2 U6.1 | length 355.3
  Top Layer w10: U6.1 -355.06,-698.6 -343.33,-710.33 R2.1 R2.1@-341.36,-714.03 ; R3.2 R2.1@-341.36,-714.03 ; C12.2 -256.71,-824.35 -331.59,-749.47 -331.59,-723.8 R2.1@-341.36,-714.03
NetC16_2: C16.2 R5.1 R6.2 U6.5 | length 330.5
  Top Layer w10: U6.5 -454.62,-566.28 -409.34,-521 R6.2 -395.41,-531 R5.1 -306.91,-442.8 C16.2
NetD3_2: D3.2 L2.2 U6.6 | length 282.9
  Top Layer w10: L2.2 -728.53,-484.69 -717.78,-495.44 -717.78,-499.15 -711.93,-505.01 D3.2@-639.2,-505.01 ; D3.2@-639.2,-491 D3.2@-639.2,-505.01 ; U6.6 -638.36,-619.86 -639.2,-619.02 D3.2@-639.2,-505.01
NetR1_1: R1.1 U4.2 | length 111.3
  Top Layer w10: R1.1 -642.2,832.82 -632.36,822.98 U4.2
SCAN: J2.27 J4.27
  other v1: -300,-991.26
SCK: J1.20 J3.20 U3.16 U4.6 | length 1206.4
  Top Layer w10: U4.6 -656.47,604.9 -656.47,548.47 -609.32,501.32 -540.65,501.32 -461.4,580.57 -461.4,817.49 -435.4,843.49 -313.24,843.49 -295.24,861.49 -173.08,861.49 -100,934.57 J1.20 -90.43,967.91 -90.43,923.25 -12.13,844.95 -12.13,825.31 -10.39,823.56 U3.16
  other v1: -100,991.26
SOURCE_SEL0: J1.26 J3.26
  other v1: -250,991.26
SOURCE_SEL1: J1.25 J3.25
  other v1: -250,1098.74
SOURCE_SEL2: J2.17 J4.17
  other v1: -50,-991.26
SOURCE_SEL3: J2.30 J4.30
  other v1: -350,-1098.74
SOURCE_SEL4: J2.26 J4.26
  other v1: -250,-1098.74
VDS_BUFF: J1.09 J3.9
  other v1: 150,1098.74
VDS_RAW: J1.10 J3.10 U3.7 | length 999
  Top Layer w10: v1(-283.43,566.74) -283.43,621.01 -240.12,664.32 -238.61,664.32 -232.91,670.02 U3.7
  Bottom Layer w10: v1(-283.43,566.74) -279.13,566.74 -212.27,633.6 121.48,633.6 210.56,722.68 210.56,868.86 150,929.42 v1(150,991.26)
VGS1: P3.1 R24.1 U7.1 U10.3 | length 1361.9
  Top Layer w10: P3.1 -596.38,-253.57 -558.96,-216.14 -475.08,-216.14 R24.1@-443.79,-184.85 ; U7.1 -808.49,139.62 -790.56,121.69 -734.12,121.69 -723.34,110.9 -723.34,48.54 -708.82,34.02 U10.3 -540.4,33.29 -514.24,33.29 -455.52,-25.42 -455.52,-173.12 R24.1@-443.79,-184.85 ; R24.1 R24.1@-443.79,-184.85
VGS1_FILT: R24.2 S1.10 | length 1479
  Top Layer w10: R24.2 -424.11,-249.81 -391.18,-282.74 3.92,-282.74 417.54,-696.36 417.54,-736.66 380.95,-773.25 380.95,-854.95 423.05,-897.05 570.76,-897.05 S1.10
VGS1_RAW: P1.1 U3.5 U7.3 | length 1270.2
  Top Layer w10: v1(-939.84,227.01) -903.63,190.8 U7.3 -853.98,190.9 -820.8,190.9 -654.76,356.94 -540.33,356.94 -348.51,548.76 -348.51,609.02 -242.03,715.5 -238.61,715.5 -232.91,721.2 U3.5
  Bottom Layer w10: P1.1 -1021.27,303.79 -944.48,227.01 v1(-939.84,227.01)
VGS1_x1: R9.1 R12.1 U7.2 U10.4 | length 686.5
  Top Layer w10: R9.1@-763.52,159.29 R9.1 -828.16,161.26 -832.1,165.21 U7.2 -855.46,163.84 -885.45,163.84 -895.71,153.58 -895.71,106.42 -815.09,25.8 ; R12.1 -762.28,74.37 -810.86,25.8 -815.09,25.8 ; U10.4 -615.17,8.43 -647.65,-24.05 -765.23,-24.05 -815.09,25.8
VGS1_x10: R12.2 U10.2 | length 150.6
  Top Layer w10: R12.2 -638.41,79.29 -618.73,59.61 U10.2
VGS2: P3.2 R27.1 U7.7 U10.6 | length 1413
  Top Layer w10: P3.2 -1056.15,-155.09 -995.38,-215.85 -584.12,-215.85 -560.92,-192.64 -538.73,-192.64 R27.1 -517.15,-180.91 -483.13,-146.89 -483.13,-74.58 -509.26,-48.46 -510.78,-48.46 -516.48,-42.75 U10.6 -615.44,-42.75 -632.73,-60.05 -780.15,-60.05 -931.71,91.51 -931.71,110.29 -982.62,161.2 -985.61,161.2 -989.62,165.21 U7.7
VGS2_FILT: R27.2 S1.13 | length 2151.3
  Top Layer w10: R27.2 -527,-282.74 -503.14,-306.6 -23.36,-306.6 384.86,-714.81 384.86,-723.1 356.64,-751.31 356.64,-869.88 512.76,-1026 663.21,-1026 837.7,-851.51 837.7,-729.27 777.06,-668.63 758.43,-668.63 S1.13
VGS2_RAW: P1.2 U3.4 U7.5 | length 1301.4
  Top Layer w10: U7.5 -1011.6,253.16 -889.82,374.94 -865.87,374.94 ; P1.2 -865.87,443.36 -865.87,374.94 ; U3.4 -248.15,746.79 -374.45,620.48 -374.45,548.27 -547.78,374.94 -865.87,374.94
VGS2_x1: R13.1 R16.1 U7.6 U10.5 | length 772.1
  Top Layer w10: R16.1@-1097.85,297.09 R13.1 -1097.85,205.73 -1082.92,190.8 U7.6 -989.62,190.8 -985.61,186.79 -982.62,186.79 -913.71,117.88 -913.71,98.97 -772.69,-42.05 -640.19,-42.05 -615.3,-17.16 U10.5
VGS2_x10: R16.2 U10.7 | length 882.2
  Top Layer w10: R16.2@-1156.91,282.33 -1131.32,256.73 -1131.32,63.54 -989.72,-78.05 -625.28,-78.05 -615.57,-68.35 U10.7
VGS3: P3.3 R22.1 U8.1 U10.11 | length 1822.1
  Top Layer w10: P3.3 -1066.77,-56.6 -938.52,-184.85 v1(-677.32,-184.85) ; v1(-278.37,-184.85) R22.1 -355.75,-184.85 -367.48,-173.12 -367.48,-163.27 -395.09,-135.67 -395.09,-96.94 -346.6,-48.46 -345.09,-48.46 -339.39,-42.75 U10.11 -50.29,-42.75 4.98,12.52 4.98,221.69 -28.14,254.82 -53.11,254.82 U8.1
  Bottom Layer w10: v1(-677.32,-184.85) v1(-278.37,-184.85)
VGS3_FILT: R22.2 S1.1 | length 1123.2
  Top Layer w10: R22.2 -336.07,-249.81 -324.33,-261.54 27.14,-261.54 528.07,-762.47 528.07,-791.43 S1.1
VGS3_RAW: P1.3 U3.6 U8.3 | length 1452.4
  Top Layer w10: U3.6 -211.94,694.89 -237.19,694.89 -316.57,615.5 v1(-316.57,462.16) -316.57,295.94 -202.26,181.63 -111.55,181.63 -87.33,205.85 -58.06,205.85 U8.3
  Bottom Layer w10: P1.3 -748.06,462.16 v1(-316.57,462.16)
VGS3_x1: R7.1 R10.1 U8.2 U10.12 | length 707.9
  Top Layer w10: U10.12 -50.16,-17.16 -13.02,19.98 -13.02,214.1 -27.71,228.8 -30.7,228.8 -34.71,232.81 U8.2 -117.93,232.81 R7.1 R10.1@-124.82,313.93
VGS3_x10: R10.2 U10.10 | length 916
  Top Layer w10: U10.10 -50.43,-68.35 22.98,5.07 22.98,246.52 -84.26,353.77 -99.54,369.05 -178.95,369.05 -189.78,358.23 R10.2@-189.78,319.84
VGS4: P4.1 R26.1 U8.7 U11.11 | length 1630.7
  Top Layer w10: U8.7 183.44,232.81 211.75,204.5 211.75,129.44 211.34,129.03 211.34,53.97 218.95,46.35 337.53,46.35 341.93,50.75 U11.11 391.22,50.75 396.92,45.05 398.44,45.05 436.71,6.78 436.71,-97.87 389,-145.58 R26.1 398.84,-180.49 428.57,-210.22 727.9,-210.22 843.2,-94.92 1077.2,-94.92 1146.39,-25.73 P4.1
VGS4_FILT: R26.2 S1.4 | length 501.2
  Top Layer w10: R26.2 389,-369.5 574.08,-554.58 620.21,-554.58 S1.4
VGS4_RAW: P2.1 U3.10 U8.5 | length 1740.7
  Top Layer w10: U3.10 84.17,670.02 144.88,609.31 144.88,553.87 v1(48.66,457.64) 0,408.98 0,301.13 42.02,259.12 42.02,204.3 64.69,181.63 U8.5 ; v1(391.35,485.7) 823.13,485.7 P2.1
  Bottom Layer w10: v1(48.66,457.64) 363.29,457.64 v1(391.35,485.7)
VGS4_x1: R14.1 R17.1 U8.6 U11.12 | length 418.8
  Top Layer w10: U8.6 151.27,207.22 179.06,179.43 R14.1 169.22,162.7 R17.1 187.84,69.27 187.84,52.01 214.69,25.16 U11.12
VGS4_x10: R17.2 U11.10 | length 151.1
  Top Layer w10: R17.2@238.12,87.89 238.12,81 R17.2@252.8,66.32 ; R17.2 298.48,87.89 310.03,76.34 U11.10
VGS5: P4.2 R23.1 U9.1 U11.3 | length 1024.5
  Top Layer w10: R23.1 544.61,-180.49 532.88,-168.75 532.88,-158.91 525,-151.03 525,-67.82 561.09,-31.72 562.61,-31.72 568.31,-26.02 U11.3 920.91,-26.02 v1@1002.21,55.28 ; v1@1009.17,62.24 U9.1
  Bottom Layer w10: v1(1003.69,53.8) 1181.71,-124.21 P4.2
VGS5_FILT: R23.2 S1.16 | length 1122.5
  Top Layer w10: R23.2 721.74,-245.45 849.93,-117.26 962,-117.26 1136.05,-291.31 1136.05,-405.95 1045,-497 915.79,-497 S1.16
VGS5_RAW: P2.2 U3.12 U9.3 | length 1508.2
  Top Layer w10: U3.12 83.9,721.2 394.1,411 871.36,411 ; U9.3 1007.8,225.73 950.09,225.73 871.36,304.46 871.36,411 ; P2.2 885.04,411 871.36,411
VGS5_x1: R8.1 R11.1 U9.2 U11.4 | length 761.6
  Top Layer w10: U11.4 907.25,-0.43 962.13,54.44 962.13,181.72 977.8,197.4 1007.8,197.4 U9.2 1076.47,198.77 1096.68,178.55 R11.1 1096.68,92.23 R8.1
VGS5_x10: R11.2 U11.2 | length 720.3
  Top Layer w10: U11.2 1026.15,-51.61 1139.19,61.43 1139.19,132.48 1175.42,168.71 R11.2
VGS6: P4.3 R25.1 U9.7 U11.6 | length 1169
  Top Layer w10: R25.1 472.14,-43.9 566.07,50.03 592.23,50.03 U11.6 659.73,50.75 v1(777.06,168.07) 806.38,197.4 850.28,197.4 U9.7
  Bottom Layer w10: v1(777.06,168.07) 777.06,167.83 1167.33,-222.45 P4.3
VGS6_FILT: R25.2 S1.7 | length 423.1
  Top Layer w10: R25.2 472.14,-283.72 547.42,-359 753.62,-359 S1.7
VGS6_RAW: P2.3 U3.11 U9.5 | length 1397.6
  Top Layer w10: U3.11 84.04,695.61 386.64,393 804.55,393 823.97,373.58 v1(826.13,373.58) ; v1@823.09,370.53 826.13,367.48 851.65,341.96 U9.5
  Bottom Layer w10: v1(826.13,373.58) 984.22,373.58 P2.3
VGS6_x1: R15.1 R18.1 U9.6 U11.5 | length 762
  Top Layer w10: U11.5 907.38,25.16 944.07,61.84 944.07,156.92 880.64,220.34 877.65,220.34 873.64,224.36 U9.6 850.28,225.73 817.64,225.73 803.67,239.7 R18.1 761.26,243.49 R15.1
VGS6_x10: R18.2 U11.7 | length 256.9
  Top Layer w10: U11.7 593.68,77.06 659.47,77.06 705.99,123.58 705.99,210.3 704.93,211.36 704.93,221.07 R18.2
VMEAS: J1.12 J3.12 U4.8 | length 1140.5
  Top Layer w10: U4.8 -604.03,603.63 v1(-558.92,603.63)
  Bottom Layer w10: v1(-558.92,603.63) -300.81,603.63 -240.12,664.32 116.57,664.32 185.43,733.18 185.43,837.42 100,922.85 v1(100,991.26)
pads on no net: J3. J4. S1.3 S1.6 S1.9 S1.12 S1.15 S1.18 S1.S1 S1.S2 S1.S3 S1.S4 U1.4 U2.4 U3.13

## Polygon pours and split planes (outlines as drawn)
GND on Bottom Layer "GND_L04_P001" (solid, pour order 1): -574.7,-598.2 -574.7,-720.25 -501.86,-720.25 -501.86,-598.2
GND on Top Layer "GND_L01_P000" (solid, pour order 0): -574.7,-598.2 -574.7,-720.25 -501.86,-720.25 -501.86,-598.2
GND on Layer 2 (split plane): 265 vertices, not listed, extent -1279.99,-1279.99 1279.99,1279.99
GND on Layer 1 (split plane): 265 vertices, not listed, extent -1279.99,-1279.99 1279.99,1279.99

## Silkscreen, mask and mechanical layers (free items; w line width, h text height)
Top Overlay:
  text "3" at -1023.32,662.59 h30
  text "4" at 917.73,617.77 h30
  text "2" at -1075.92,581.97 h30
  text "5" at 967,514 h30
  text "1" at -1120.38,505.38 h30
  text "VGS RAW" at 718.47,477.71 h30
  text "VGS RAW" at -914.27,464.64 h30
  text "6" at 1016.17,431 h30
  text "4" at 1114.87,-25.93 h30
  text "VGS x1/x10" at 789.58,-79.06 h30
  text "3" at -1243.47,-86.94 h30
  text "VGS x1/x10" at -1037.7,-118.24 h30
  text "5" at 1099.06,-127.29 h30
  text "2" at -1236.75,-190.64 h30
  text "6" at 1078.49,-219.74 h30
  text "1" at -1203.06,-287.11 h30
  text "OFF" at 1017.48,-574.38 h30
  text "ON" at 784.06,-886.09 h30
Bottom Overlay:
  text "Breathalyzer- Amplifier" at 509.08,44.08 h60
  text "Neel Mondal         Palacios Group, MIT   April 2023" at 509.08,-218.13 h40
Board:
  circle w5: c0,0 r1300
